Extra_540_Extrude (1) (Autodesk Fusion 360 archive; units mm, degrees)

design "Extra_540_Extrude" references "Extra_540_wheel", "MOTOR_PROP", "Motor_mount_Inter", "Extra_540_freeform_Undercarriage"
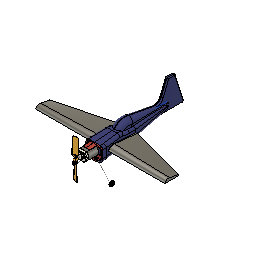
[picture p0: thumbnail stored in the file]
canvas "Canvas1"
canvas "Canvas2"
canvas "Canvas3"
sketch "Sketch10" plane through (0, 0, 0) normal (1, 0, 0) x axis (0, 0, -1)
  dimension "d51" = 50.55
extrude "Extrude4" new body sketch "Sketch10" along normal blind 16
sketch "Sketch11" plane through (0, 0, 0) normal (0, 1, 0) x axis (1, 0, 0)
extrude "Extrude5" cut sketch "Sketch11" no distance stored
fillet "Fillet8" radius 10
fillet "Fillet17" radius 19
fillet "Fillet14" radius 5
sketch "Sketch14" plane through (0, 0, 0) normal (1, 0, 0) x axis (0, 0, -1)
extrude "Extrude6" new body sketch "Sketch14" along normal blind 10
sketch "Sketch15" plane through (0, 0, 0) normal (0, 1, 0) x axis (1, 0, 0)
extrude "Extrude7" cut sketch "Sketch15" no distance stored
fillet "Fillet6" StartRadius 9 EndRadius 1
work_plane "WorkPlane5"
sketch "Sketch16" plane through (9.553, 13.2876, -113.5643) normal (0, 0.2935, 0.956) x axis (1, 0, 0)
  dimension "d43" = 20
revolve "Revolve2" sketch "Sketch16" AlongAngle 110
sketch "Sketch17" plane through (0, 0, 0) normal (1, 0, 0) x axis (0, 0, -1)
extrude "Extrude8" add sketch "Sketch17" along normal blind 3
sketch "Sketch18" plane through (0, 0, 0) normal (1, 0, 0) x axis (0, 0, -1)
  dimension "d60" = 2
sketch "Sketch19" plane through (0, 0, 0) normal (1, 0, 0) x axis (0, 0, -1)
  dimension "d62" = 2
  dimension "d52" = 20.65
extrude "Extrude9" cut sketch "Sketch19" + "Sketch18" no distance stored
ground "Ground1"
component_insert "Component Insert2"
ground "Ground2"
component_insert "Component Insert7"
joint "Assemble3" OffsetX 0 OffsetY 0 OffsetZ 0 AngleZ 0 OffsetX 0 OffsetY 0 OffsetZ 0 AngleZ 0 alignAngle 180 alignOffsetX 0 alignOffsetY 0 alignOffsetZ 0
sketch "Sketch1" plane through (0, 0, 0) normal (1, 0, 0) x axis (0, 0, -1)
extrude "Extrude1" new body sketch "Sketch1" distance 16
work_plane "WorkPlane1" AlongDistance 110
sketch "Sketch2" plane through (126, 0.6226, -89.2404) normal (1, 0, 0) x axis (0, 0, -1)
  dimension "d4" = 2
  dimension "d5" = 27.5
loft "Loft1" sketch "Sketch2"
mirror "Mirror1"
sketch "Sketch1" plane through (0, 6.3519, 0) normal (0, 1, 0) x axis (-1, 0, 0)
extrude "Extrude1" new body sketch "Sketch1" along normal blind 2
component_insert "Component Insert3"
ground "Ground3"
ground "Ground5"
component_insert "Component Insert4"
ground "Ground6"
component_insert "Component Insert5"
joint "Assemble1" OffsetX 0 OffsetY 0 OffsetZ 0 AngleZ 0 OffsetX 0 OffsetY 0 OffsetZ 0 AngleZ 0 alignAngle -90 alignOffsetX 0 alignOffsetY 0 alignOffsetZ -2
component_insert "Component Insert6"
joint "Assemble2" OffsetX 0 OffsetY 0 OffsetZ 0 AngleZ 0 OffsetX 0 OffsetY 0 OffsetZ 0 AngleZ 0 alignAngle -90 alignOffsetX 0 alignOffsetY 0 alignOffsetZ -1.5
ground "Ground7"
position "Position2"
ground "Ground8"
ground "Ground9"
position "Position3"
ground "Ground10"
ground "Ground11"
ground "Ground12"
fillet "Fillet18" radius 3
fillet "Fillet16" radius 2
mirror_component "MirrorComponent1"
remove_instance "RemoveInstance2"
mirror_component "MirrorComponent2"
derived_instance "DerivedInstance2"
sketch "Sketch2" plane through (0, 0, 0) normal (1, 0, 0) x axis (0, 0, -1)
extrude "Extrude1" new body sketch "Sketch2" along normal blind 16
work_plane "WorkPlane1" AlongDistance 125
sketch "Sketch3" plane through (125, 0, 0) normal (1, 0, 0) x axis (0, 0, -1)
  dimension "d79" = 2
  dimension "d80" = 27.0412
  dimension "d81" = 1.8577
  dimension "d82" = 5.3463
loft "Loft1" sketch "Sketch3"
mirror "Mirror1"
sketch "Sketch1" plane through (0, 6.3519, 0) normal (0, 1, 0) x axis (-1, 0, 0)
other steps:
derived_base_feature "Derived Base Feature"
create_component "CreateComponent1"
create_component "CreateComponent2"
create_component "CreateComponent3"
create_component "CreateComponent7"
create_component "CreateComponent8"
create_component "CreateComponent9"

design "Extra_540_freeform_Undercarriage"
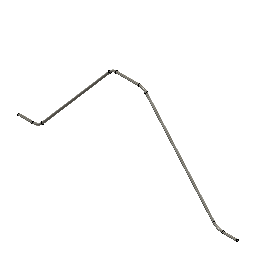
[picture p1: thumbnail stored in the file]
base_feature "Base Feature"
sketch "Path (1)" plane through (0, 0, -48.1) normal (0, 0, 1) x axis (1, 0, 0)
  dimension "d165" = 5
  dimension "d166" = 4
  dimension "d178" = 0
  dimension "d179" = 0
  dimension "d180" = 0
  dimension "d181" = 0
  dimension "d190" = 0
  dimension "d191" = 0
  dimension "d192" = 0
  dimension "d193" = 0
sketch "Profile" plane through (0, 0, 0) normal (1, 0, 0) x axis (0, 0, -1)
  circle C1 centre (47.7, -10.2807) radius 0.375
  dimension "d167" diameter C1 = 0.75
sweep "Sweep1" sketch "Profile" TwistAngle 0 TaperAngle 0

design "Propeller_2-5_x_1"
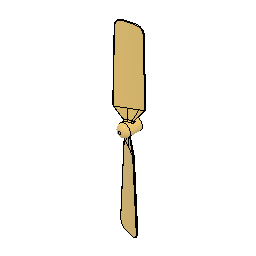
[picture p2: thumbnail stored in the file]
sketch "Sketch1" plane through (0, 0, 0) normal (1, 0, 0) x axis (0, 0, -1)
  dimension "d1" = 1
  dimension "d2" = 2.5
  dimension "d3" = 2
  dimension "d5" = 7
  dimension "d6" = 115
  dimension "d7" = 1.5
revolve "Revolve1" sketch "Sketch1" AlongAngle 360
work_plane "WorkPlane1" AlongDistance 38
sketch "Sketch2" plane through (0, 38, 0) normal (0, 1, 0) x axis (1, 0, 0)
  dimension "d10" = 3
  dimension "d11" = 10
  dimension "d12" = 0.5
  dimension "d13" = 10
work_plane "WorkPlane2" AlongDistance 7
sketch "Sketch3" plane through (0, 7, 0) normal (0, 1, 0) x axis (1, 0, 0)
  dimension "d15" = 10
  dimension "d16" = 0.5
  dimension "d17" = 30
sketch "Sketch4" plane through (0, 0, 0) normal (1, 0, 0) x axis (0, 0, -1)
sweep "Sweep1" sketch "Sketch3" TwistAngle -15 TaperAngle 0
sketch "Sketch5" plane through (0, 0, 0) normal (0, 1, 0) x axis (1, 0, 0)
  dimension "d24" = 0.5
  dimension "d25" = 1
  dimension "d26" = 60
sketch "Sketch6" plane through (0, 0, 0) normal (1, 0, 0) x axis (0, 0, -1)
loft "Loft2" sketch "Sketch5" + "Sketch3"
fillet "Fillet2" radius 3
fillet "Fillet3" radius 2
fillet "Fillet4" radius 0.2
fillet "Fillet5" radius 0.5
circular_pattern "C-Pattern1" TotalAngle 360

design "Motor_body"
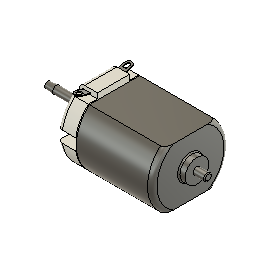
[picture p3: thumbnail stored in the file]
sketch "Sketch1" plane through (0, 0, 0) normal (1, 0, 0) x axis (0, 0, -1)
  dimension "d1" = 20.1
  dimension "d2" = 15.1
extrude "Extrude1" new body sketch "Sketch1" along normal blind 20
sketch "Sketch2" plane through (0, 0, 0) normal (-1, 0, 0) x axis (0, 0, 1)
  dimension "d5" = 1
extrude "Extrude2" add sketch "Sketch2" along normal blind 0.25
sketch "Sketch1"
sketch "Sketch2" plane through (0, 0, 0) normal (1, 0, 0) x axis (0, 0, -1)
work_plane "WorkPlane1"
sketch "Sketch3" plane through (-0.25, 6.55, 6.245) normal (1, 0, 0) x axis (0, 0, -1)
  dimension "d8" = 8.5
  dimension "d9" = 1.4
extrude "Extrude1" new body sketch "Sketch3" against normal blind 4.75
sketch "Sketch4" plane through (-5, 0, 0) normal (-1, 0, 0) x axis (0, 0, 1)
  dimension "d12" = 10
  dimension "d13" = 4
extrude "Extrude2" add sketch "Sketch4" along normal blind 2.3
sketch "Sketch3" plane through (20, 0, 0) normal (1, 0, 0) x axis (0, 0, -1)
  dimension "d16" = 6.15
extrude "Extrude3" add sketch "Sketch3" along normal blind 1.7
sketch "Sketch1" plane through (-7.3, 0, 0) normal (-1, 0, 0) x axis (0, 0, 1)
  dimension "d19" = 2
extrude "Extrude1" new body sketch "Sketch1" along normal blind 10.3
sketch "Sketch2" plane through (21.7, 0, 0) normal (1, 0, 0) x axis (0, 0, -1)
  circle C1 centre (0, 0) radius 3.075
extrude "Extrude4" cut of existing geometry blind -42.3
work_plane "WorkPlane1" AlongDistance 2
sketch "Sketch1" plane through (-2, 0, 0) normal (-1, 0, 0) x axis (0, 0, -1)
  dimension "d29" = 3.25
  dimension "d30" = 0.2
  dimension "d31" = 15
extrude "Extrude1" new body sketch "Sketch1" along normal blind 2
fillet "Fillet1" radius 1
sketch "Sketch2" plane through (0, 6.4116, 1.718) normal (0, 0.9659, 0.2588) x axis (1, 0, 0)
  dimension "d36" = 1.5
  dimension "d37" = 0.5
extrude "Extrude2" cut sketch "Sketch2" to an object
sketch "Sketch3" plane through (0, 6.4116, -1.718) normal (0, 0.9659, -0.2588) x axis (-1, 0, 0)
  dimension "d41" = 1.5
  dimension "d42" = 0.5
extrude "Extrude3" cut sketch "Sketch3" to an object
sketch "Sketch5" plane through (-5, 0, 0) normal (-1, 0, 0) x axis (0, 0, 1)
  dimension "d45" = 6
  dimension "d46" = 1
  dimension "d47" = 1
  dimension "d48" = 7
extrude "Extrude4" add sketch "Sketch5" along normal blind 0.1
sketch "Sketch6" plane through (-5, 0, 0) normal (-1, 0, 0) x axis (0, 0, 1)
  dimension "d51" = 3
  dimension "d52" = 4.825
extrude "Extrude5" cut sketch "Sketch6" to an object
chamfer "Chamfer1" distance 0.2 rotateAngle 85
fillet "Fillet1" radius 1.25
fillet "Fillet1" radius 1.25
extrude "Extrude3" add of existing geometry blind 32
chamfer "Chamfer1" distance 0.5 rotateAngle 45
fillet "Fillet2" radius 1.4
fillet "Fillet2" radius 0.3
fillet "Fillet1" radius 0.25
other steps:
create_component "CreateComponent1"
create_component "CreateComponent2"
extrude "Extrude3" cut of existing geometry blind -42.3
extrude "Extrude2" cut of existing geometry blind -42.3
create_component "CreateComponent3"

design "Motor_mount_Inter"
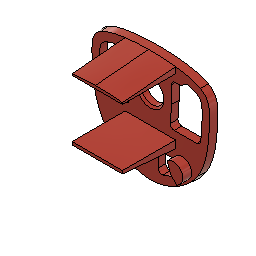
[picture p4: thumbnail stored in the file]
base_feature "Base Feature"
work_plane "WorkPlane1" AlongDistance -50.1
sketch "Sketch3" plane through (0, 0, -50.1) normal (0, 0, 1) x axis (1, 0, 0)
extrude "Extrude1" new body sketch "Sketch3" along normal blind 2 taper -5
sketch "Sketch4" plane through (0, 0, -48.1) normal (0, 0, 1) x axis (1, 0, 0)
  dimension "d89" = 2
extrude "Extrude2" add sketch "Sketch4" along normal blind 14
draft "Draft1" Angle1 5 Angle2 0
sketch "Sketch5" plane through (0, 0, -48.1) normal (0, 0, 1) x axis (1, 0, 0)
extrude "Extrude3" cut sketch "Sketch5" no distance stored
chamfer "Chamfer1" distance 0.5
draft "Draft2" Angle1 5 Angle2 0
sketch "Sketch6" plane through (0, 0, -48.1) normal (0, 0, 1) x axis (1, 0, 0)
  dimension "d101" = 2
  dimension "d102" = 2.5
extrude "Extrude4" cut sketch "Sketch6" no distance stored
fillet "Fillet1" radius 1
sketch "Sketch7" plane through (0, 0, -48.1) normal (0, 0, 1) x axis (1, 0, 0)
  dimension "d141" = 4
  dimension "d143" = 4
  dimension "d144" = 2.5
extrude "Extrude5" add sketch "Sketch7" along normal blind 2.5
fillet "Fillet2" radius 1
sketch "Sketch8" plane through (4.0871, 0, 0) normal (1, 0, 0) x axis (0, 0, -1)
sketch "Sketch9" plane through (4.0871, 0, 0) normal (1, 0, 0) x axis (0, 0, -1)
  dimension "d148" = 0.4
  dimension "d149" = 0.8
extrude "Extrude6" cut sketch "Sketch9" to an object
sketch "Sketch10" plane through (0, 0, -48.1) normal (0, 0, 1) x axis (1, 0, 0)
  dimension "d154" = 29.9506
  dimension "d155" = 26.0609
  dimension "d161" = 2.5
  dimension "d162" = 3.5
extrude "Extrude7" add sketch "Sketch10" along normal blind 0.8
sketch "Sketch11" plane through (0, 0, -47.3) normal (0, 0, 1) x axis (1, 0, 0)
  dimension "d164" = 1
extrude "Extrude8" add sketch "Sketch11" along normal blind 1.5

design "Extra_540_wheel"
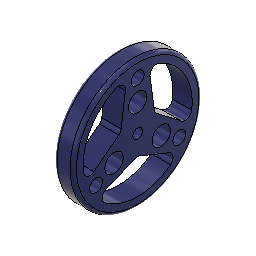
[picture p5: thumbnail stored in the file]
sketch "Sketch1" plane through (0, 0, 0) normal (1, 0, 0) x axis (0, 0, -1)
  dimension "d1" = 0.75
  dimension "d2" = 10
  dimension "d5" = 1
  dimension "d6" = 0.4
  dimension "d7" = 2
extrude "Extrude1" new body sketch "Sketch1" along normal blind 1.5
fillet "Fillet1" radius 0.5
fillet "Fillet2" radius 0.25

design "MOTOR_PROP" references "Motor_body", "Propeller_2-5_x_1"
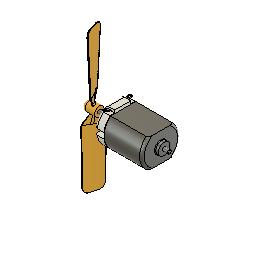
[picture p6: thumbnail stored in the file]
component_insert "Component Insert1"
as_built_joint "As-built1"
component_insert "Component Insert2"
joint "Assemble2" OffsetX 0 OffsetY 0 OffsetZ 0 AngleZ 0 OffsetX 0 OffsetY 0 OffsetZ 0 AngleZ 0 alignAngle 0 alignOffsetX 0 alignOffsetY 0 alignOffsetZ 0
